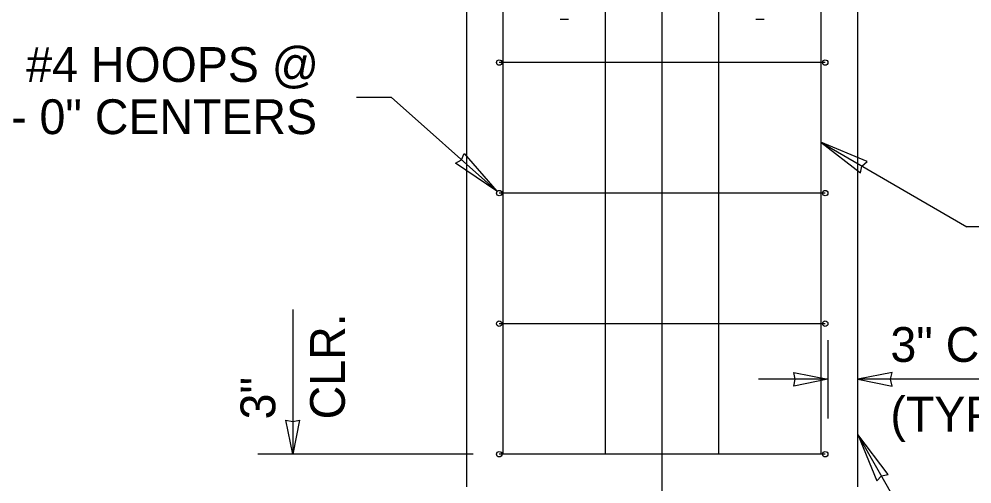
# Model space of a CAD drawing. Extents: x 99862 to 103151, y 100000 to 102076.
# Drawn here: x 100086.3 to 100524.7, y 101325.3 to 101539 of the extents above; entities that cross this region are included whole.
import ezdxf

# ---------------------------------------------------------------- set-up
doc = ezdxf.new("R2010")
doc.units = 0
for name, color, linetype in [('Level 13', 7, 'Continuous'), ('Level 15', 7, 'Continuous'), ('Level 2', 7, 'Continuous'), ('Level 20', 7, 'Continuous'), ('Level 23', 7, 'Continuous')]:
    doc.layers.add(name, color=color, linetype=linetype)

msp = doc.modelspace()

# ---------------------------------------------------------------- linework, layer by layer
at = {"layer": 'Level 13'}
for p, q in [((100309.05, 101338.99), (100309.05, 101798.99)), ((100356.13, 101338.99), (100356.13, 101798.99)), ((100408.21, 101338.99), (100408.21, 101798.99)), ((100455.3, 101338.99), (100455.3, 101798.99)), ((100457.17, 101518.99), (100307.17, 101518.99)), ((100457.17, 101458.99), (100307.17, 101458.99)), ((100457.17, 101398.99), (100307.17, 101398.99)), ((100457.17, 101338.99), (100307.17, 101338.99))]:
    msp.add_line(p, q, dxfattribs=at)
for centre in [(100307.17, 101518.99), (100457.17, 101518.99), (100307.17, 101458.99), (100457.17, 101458.99), (100307.17, 101398.99), (100457.17, 101398.99), (100307.17, 101338.99), (100457.17, 101338.99)]:
    msp.add_circle(centre, 1.25, dxfattribs=at)
at = {"layer": 'Level 15'}
for p, q in [((100382.17, 101307.99), (100382.17, 102008.07)), ((100241.49, 101503.11), (100257.49, 101503.11)), ((100306.12, 101459.87), (100257.49, 101503.11)), ((100455.19, 101482.34), (100522.4, 101443.54)), ((100538.44, 101443.54), (100522.4, 101443.54)), ((100212.17, 101405.49), (100212.17, 101338.99)), ((100458.42, 101391.43), (100458.42, 101355.43)), ((100458.42, 101373.43), (100426.42, 101373.43)), ((100565.6, 101373.43), (100472.17, 101373.43)), ((100524.64, 101256.61), (100472.17, 101348)), ((100295.17, 101338.99), (100196.17, 101338.99))]:
    msp.add_line(p, q, dxfattribs=at)
for points in [[(100455.19, 101482.34), (100473.47, 101468.34), (100474.04, 101471.45), (100476.45, 101473.51)], [(100306.12, 101459.87), (100287.08, 101472.81), (100289.85, 101474.34), (100291.05, 101477.27)], [(100458.42, 101373.43), (100442.7, 101370.34), (100443.42, 101373.43), (100442.7, 101376.51)], [(100472.17, 101373.43), (100487.9, 101370.34), (100487.17, 101373.43), (100487.9, 101376.51)], [(100212.17, 101338.99), (100209.09, 101354.71), (100212.17, 101353.98), (100215.25, 101354.71)], [(100472.17, 101348), (100480.95, 101326.71), (100483.01, 101329.11), (100486.13, 101329.68)]]:
    msp.add_lwpolyline(points, close=True, dxfattribs=at)
at = {"layer": 'Level 2'}
for p, q in [((100292.17, 101803.99), (100292.17, 101323.99)), ((100472.17, 101323.99), (100472.17, 101803.99))]:
    msp.add_line(p, q, dxfattribs=at)
at = {"layer": 'Level 23'}
for p, q in [((100335.27, 101538.99), (100339.07, 101538.99)), ((100425.27, 101538.99), (100429.07, 101538.99))]:
    msp.add_line(p, q, dxfattribs=at)

# ---------------------------------------------------------------- texts
at = {"layer": 'Level 20'}
for s, p in [('#4 HOOPS @', (100089.58, 101510.11)), ('1\' - 0" CENTERS', (100060.7, 101486.11)), ('3" CLR.', (100487.17, 101381.43)), ('(TYP.)', (100487.17, 101349.43))]:
    msp.add_text(s, height=16, dxfattribs=at).set_placement(p)
for s, p in [('CLR.', (100236.17, 101354.99)), ('3"', (100204.17, 101354.99))]:
    msp.add_text(s, height=16, rotation=90, dxfattribs=at).set_placement(p)

doc.saveas('drawing.dxf')
